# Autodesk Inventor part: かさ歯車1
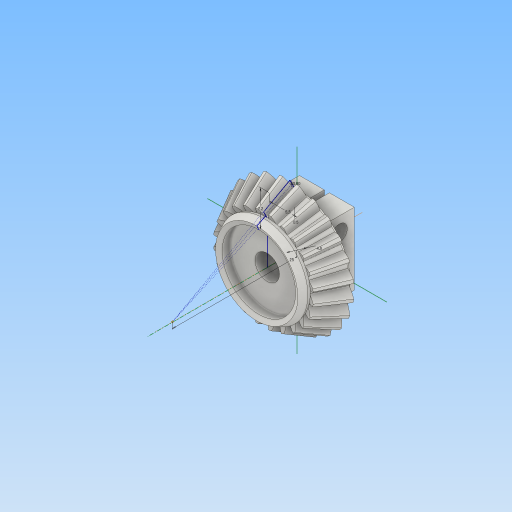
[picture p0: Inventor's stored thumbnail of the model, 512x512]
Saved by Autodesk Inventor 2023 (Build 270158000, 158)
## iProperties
CustomPartVersion: 1
Created: 2024-01
Part Number: かさ歯車1
Material: Steel, Mild
Document SubType Name: Modeling
Designer: kumagai
Categories: <?xml version="1.0" encoding="UTF-16"?> <MemberInstance><Categories><FamilyTemplate><FamilyTemplateParameter ValueType="xs:double" Id="1" ObjectReferenceKey="da
Mass: 60.9118 g
Surface Area: 34.3074 cm^2
Volume: 7.7496 cm^3
Density: 7.86 g/cm^3
Appearance: Steel
Author: kumagai
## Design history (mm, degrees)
node "上側の点"
node "メッシュ平面2"
sketch "歯のボディ スケッチ"
  geometry: L1 (0, 0)-(10.927, -24.537); L2 (10.927, -24.537)-(12.894, -23.553); L3 (12.894, -23.553)-(0, 0); L4 (12, -24)-(0, 0); L5 (8.483, -19.05)-(10.011, -18.286); L6 (10.927, -24.537)-(8.483, -19.05); L7 (12.894, -23.553)-(10.011, -18.286); L8 (0, -29.444)-(0, 4.907) reference; L9 (0, -24)-(12.894, -24); L10 (9.138, -18.723)-(8.243, -16.934); L11 (8.243, -16.934)-(7.349, -17.381); L12 (7.349, -19.617)-(7.349, -19.617); L13 (7.349, -19.617)-(9.138, -18.723); L14 (7.349, -17.381)-(7.349, -19.617); 3 further points
  constraints: 26 end point, 4 parallel, 4 point on line, 3 collinear, 3 perpendicular, 1 horizontal alignment, 1 vertical alignment
  dimensions: "d0" = 24 diameter of L4.start L8 (= da_de); "d1" = 21.85337 diameter of L1.end L8 (= da_dfe); "d2" = 25.78885 diameter of L2.end L8 (= da_dae); "d3" = 6 distance between parallel lines of L2 L5 (= da_b); "d4" = 23.55279 vertical distance of L2.end L1.start (= da_ve); "d94" = 0.2 distance between parallel lines of L4 L10; "d95" = 0 distance between parallel lines of L5 L13; "d96" = 2 distance between parallel lines of L13 L11; "d97" = 2 distance between parallel lines of L12 L10; "d100" = 1 distance from line of L11.end L10
revolve "歯のボディ" stored, may be unused: angle "d5" = 90 deg
node "始点"
node "歯の平面"
sketch "開始スケッチ"
  geometry: L1 (0, -16.434)-(0, 4.689) reference; L2 (-0.407, -1.464)-(0.407, -1.464); A1 r 4.929 centre (-5.305, -2.008) between (-0.407, -1.464) and (-1.886, 1.542); A2 r 4.929 centre (5.305, -2.008) between (1.886, 1.542) and (0.407, -1.464); A3 r 15.076 centre (0, -13.416) between (1.886, 1.542) and (-1.886, 1.542); 1 further point
  constraints: 6 point on circle, 3 centre point, 3 symmetric about line, 2 end point, 1 coincident, 1 perpendicular, 1 other
  dimensions: "d7" = 4.92852 radius of A1 (= fd_rr); "d8" = 5.30503 horizontal distance of point (0, -13.416) A1.centre (= fd_x); "d9" = 11.4085 vertical distance of point (0, -13.416) A1.centre (= fd_y); "d57" = 15.07641 radius of A3 (= 0.5 x fd_dva + 0.3 x da_he); "d58" = 11.95241 distance from line of A3.centre L2 (= 0.5 x fd_dva - 1.12 x da_he)
node "終了側の点"
  node "終了平面"
sketch "終了側スケッチ"
  geometry: L1 (0, -12.692)-(0, 3.621) reference; L2 (-0.314, -1.131)-(0.314, -1.131); A1 r 3.806 centre (-4.097, -1.551) between (-0.314, -1.131) and (-1.456, 1.191); A2 r 3.806 centre (4.097, -1.551) between (1.456, 1.191) and (0.314, -1.131); A3 r 11.643 centre (0, -10.361) between (1.456, 1.191) and (-1.456, 1.191); 1 further point
  constraints: 6 point on circle, 3 centre point, 3 symmetric about line, 2 end point, 1 coincident, 1 other
  dimensions: "d12" = 3.80627 radius of A1 (computed from fd_rr, fd_ratio); "d15" = 4.09704 horizontal distance of A1.centre point (0, -10.361) (computed from fd_x, fd_ratio); "d16" = 8.81071 vertical distance of A1.centre point (0, -10.361) (computed from fd_y, fd_ratio); "d59" = 11.64342 radius of A3 (computed from d57, fd_ratio); "d60" = 9.23077 distance from line of A3.centre L2 (computed from d58, fd_ratio)
feature "Loft" sketch "終了側スケッチ" dims "d17" = 0, "d18" = 90 deg, "d19" = 0, "d20" = 90 deg, "d89" = 0, "da_teethtype" = 0 [user parameter]
sketch "3D スケッチ(右)"
  node "Helical Curve Right" dims "d65" = 164.5695 (computed from da_dm, da_delta, da_beta), "d66" = 31.5, "d67" = 24 (= da_de), "d68" = -4.63648 (= -da_delta), "d69" = 5.46495 (computed from fd_loft, da_delta)
node "終了平面(右)"
sketch "終了側スケッチ(右)"
  geometry: L1 (0, -14.771)-(0, 5.7) reference; L2 (-0.314, -1.131)-(0.314, -1.131); A1 r 3.806 centre (-4.097, -1.551) between (-0.314, -1.131) and (-1.456, 1.191); A2 r 3.806 centre (4.097, -1.551) between (1.456, 1.191) and (0.314, -1.131); A3 r 11.643 centre (0, -10.361) between (1.456, 1.191) and (-1.456, 1.191); 1 further point
  constraints: 6 point on circle, 3 centre point, 3 symmetric about line, 2 end point, 1 coincident, 1 perpendicular, 1 other
  dimensions: "d70" = 4.09704 horizontal distance of A3.centre A1.centre (computed from fd_x, fd_ratio); "d71" = 8.81071 vertical distance of point (0, -10.361) A1.centre (computed from fd_y, fd_ratio); "d72" = 3.80627 radius of A1 (computed from fd_rr, fd_ratio); "d73" = 9.23077 distance from line of point (0, -10.361) L2 (computed from d58, fd_ratio); "d74" = 11.64342 radius of A3 (computed from d57, fd_ratio)
feature "ロフト(右)" sketch "終了側スケッチ(右)" dims "d75" = 0, "d77" = 0, "d79" = 0, "d80" = 90 deg, "d85" = 20, "d92" = 90 deg, "d93" = 90 deg, "da_teethtype" = 0 [user parameter]
sketch "3D スケッチ(左)"
  node "Helical Curve Left" dims "d26" = 164.5695 (computed from da_dm, da_delta, da_beta), "d27" = 5.46495 (computed from fd_loft, da_delta), "d28" = 24 (= da_de), "d29" = -4.63648 (= -da_delta)
node "終了平面(左)"
sketch "終了側スケッチ(左)" dims "d56" = 8.95418 (derived)
  geometry: L1 (0, -25.921)-(0, 10.079) reference; L2 (-0.314, -1.131)-(0.314, -1.131); A1 r 3.806 centre (-4.097, -1.551) between (-0.314, -1.131) and (-1.456, 1.19); A2 r 3.806 centre (4.097, -1.551) between (1.456, 1.19) and (0.314, -1.131); A3 r 11.643 centre (0, -10.362) between (1.456, 1.19) and (-1.456, 1.19); 2 further points; 1 other entity
  constraints: 6 point on circle, 3 centre point, 3 symmetric about line, 2 end point, 1 coincident, 2 other
  dimensions: "d30" = 3.80627 radius of A1 (computed from fd_rr, fd_ratio); "d31" = 4.09704 horizontal distance of point (0, -10.362) A1.centre (computed from fd_x, fd_ratio); "d32" = 8.81071 vertical distance of A1.centre point (0, -10.362) (computed from fd_y, fd_ratio); "d61" = 11.64342 radius of A3 (computed from d57, fd_ratio); "d62" = 9.23077 distance from line of point (0, -10.362) L2 (computed from d58, fd_ratio)
feature "ロフト(左)" sketch "終了側スケッチ(左)" dims "d35" = 0, "d37" = 0, "d39" = 0, "d40" = 90 deg, "d84" = 10, "d90" = 90 deg, "d91" = 90 deg, "da_teethtype" = 0 [user parameter]
sketch "ボディ スケッチ"
  geometry: L1 (0, -25.634)-(0, -17.953) reference; L2 (10.927, -24.537)-(8.483, -19.05) reference; L3 (8.483, -19.05)-(0, -19.05); L4 (10.927, -24.537)-(0, -24.537); L5 (10.927, -24.537)-(10.659, -25); L6 (10.659, -25)-(0, -25); L7 (0, -25)-(0, -24.537); 1 further point
  constraints: 10 end point, 3 point on line, 2 perpendicular, 1 horizontal
  dimensions: "d104" = 25 distance from line of point (0, 0) L6; "d105" = 60 deg angle of L6 L5
revolve "固定ボディ" stored, may be unused: angle "d46" = 90 deg
sketch "Sketch6"
  geometry: L1 (12, -24)-(0, 0) reference; L2 (0, -28.8)-(0, 4.8) reference
feature "ピッチ円直径" sketch "Sketch6" dims angle "d47" = 90 deg
revolve "回転3" stored, may be unused: angle "d98" = 90 deg
chamfer "面取り1" distance "d101" = 0.5; stored, may be unused: second distance "d102" = 0.4, angle "d103" = 45 deg
revolve "回転4" stored, may be unused: angle "d106" = 360 deg
sketch "スケッチ8"
  geometry: L1 (0, -17.985)-(0, 17.985) reference; L2 (-17.985, 0)-(17.985, 0) reference; L3 (0.5, 7.2)-(5.5, 7.2); L4 (5.5, 7.2)-(5.5, -7.2); L5 (5.5, -7.2)-(0.5, -7.2); L6 (0.5, -7.2)-(0.5, -2.398); L7 (0.5, 2.398)-(0.5, 7.2); A1 r 2.45 centre (0, 0) between (0.5, 2.398) and (0.5, -2.398); 1 further point
  constraints: 10 end point, 2 point on circle, 1 centre point, 1 coincident, 1 collinear, 1 horizontal, 1 other
  dimensions: "d107" = 4.9 diameter of A1; "d108" = 0.5 distance between parallel lines of L1 L7; "d109" = 5.5 distance between parallel lines of L1 L4; "d110" = 7.2 distance between parallel lines of L2 L3
extrude "押し出し1" cut sketch "スケッチ8" distance "d111" = 10; taper "d112" = 0 deg
extrude "押し出し2" join sketch "スケッチ8" distance "d113" = 6; taper "d114" = 0 deg
sketch "スケッチ9"
  geometry: L1 (-17.985, -25)-(17.985, -25) reference; L2 (0, 6.2)-(0, -37.2) reference; L3 (0, -37.2)-(0, 6.2) reference; C1 r 1.6 at (4.2, -28); C2 r 1.6 at (-4.2, -28); 1 further point
  constraints: 2 centre point, 1 other
  dimensions: "d115" = 3.2 diameter of C2; "d116" = 4.2 distance from line of L2 C2.centre; "d117" = 3 distance from line of C2.centre L1
extrude "押し出し3" cut sketch "スケッチ9" extent not by distance; stored distance "d118" = 0; taper "d119" = 0 deg
pattern_circular "円形状パターン4" dims angle "d121" = 360 deg
body "Solid1"
pattern_circular "Circular Pattern" dims angle "d22" = 360 deg, "d88" = 0, "da_teethtype" = 0 [user parameter]
pattern_circular "放射状パターン(右)" dims angle "d82" = 360 deg, "da_teethtype" = 0 [user parameter]
pattern_circular "放射状パターン(左)" dims angle "d42" = 360 deg, "da_teethtype" = 0 [user parameter]
body "Srf1"
node "ソリッド2"
node "ソリッド3"
other parameters: "da_b" = 6 [user parameter; used in 2 equation terms], "da_de" = 24 [user parameter; used in 4 equation terms], "da_dae" = 25.78885 [user parameter; used in 2 equation terms], "da_dfe" = 21.85337 [user parameter; used in 1 equation term], "da_le" = 26.83282 [user parameter; used in 1 equation term], "da_omega" = 90 deg [user parameter; used in 1 equation term], "da_beta" = 0 [user parameter; used in 2 equation terms], "da_delta" = 4.63648 [user parameter; used in 8 equation terms], "da_alpha" = 20 deg [user parameter; used in 2 equation terms], "da_he" = 2.2 [user parameter; used in 4 equation terms], "da_ve" = 23.55279 [user parameter; used in 1 equation term], "fd_dv" = 26.83282 (computed from da_de, da_delta) [user parameter; used in 1 equation term], "fd_dva" = 28.83282 (computed from da_dae, da_delta) [user parameter; used in 3 equation terms], "fd_dvb" = 25.2146 (computed from fd_dv, da_alpha) [user parameter; used in 2 equation terms], "da_zv" = 268.32816 [user parameter; used in 1 equation term], "fd_loft" = 6.11 (= da_b + 0.05 x da_he) [user parameter; used in 4 equation terms], "fd_ratio" = 7.72294 (computed from da_le, fd_loft) [user parameter; used in 15 equation terms], "fd_rr" = 4.92852 (computed from fd_dd, fd_dvb) [user parameter; used in 6 equation terms], "fd_angle" = 0.59191 (computed from da_zv) [user parameter; used in 4 equation terms], "fd_x1" = 0.79366 (computed from da_dvw, fd_angle) [user parameter; used in 1 equation term], "fd_y1" = 13.39291 (computed from da_dvw, fd_angle) [user parameter; used in 1 equation term], "fd_x2" = 4.51137 (computed from fd_rr, fd_angle2, fd_angle) [user parameter; used in 1 equation term], "fd_y2" = 1.98441 (computed from fd_rr, fd_angle2, fd_angle) [user parameter; used in 1 equation term], "fd_x" = 5.30503 (= fd_x1 + fd_x2) [user parameter; used in 4 equation terms], "fd_y" = 11.4085 (= fd_y1 - fd_y2) [user parameter; used in 4 equation terms], "fd_angle2" = 3.55206 (computed from fd_dvb, fd_dd, da_alpha) [user parameter; used in 2 equation terms], "fd_dd" = 27.07282 (= fd_dva - 0.8 x da_he) [user parameter; used in 2 equation terms], "da_dvw" = 26.83282 [user parameter; used in 2 equation terms], "d11" = 6.11 (= fd_loft), "da_dm" = 21.31672 [user parameter; used in 2 equation terms], "da_x" = 0 [user parameter], "da_m" = 1 [user parameter], "d48" = 0, "d49" = 0, "d50" = 90 deg (= da_omega), "d51" = 7.5 deg (computed from da_z), "d52" = 0, "d53" = 0, "d54" = 0
